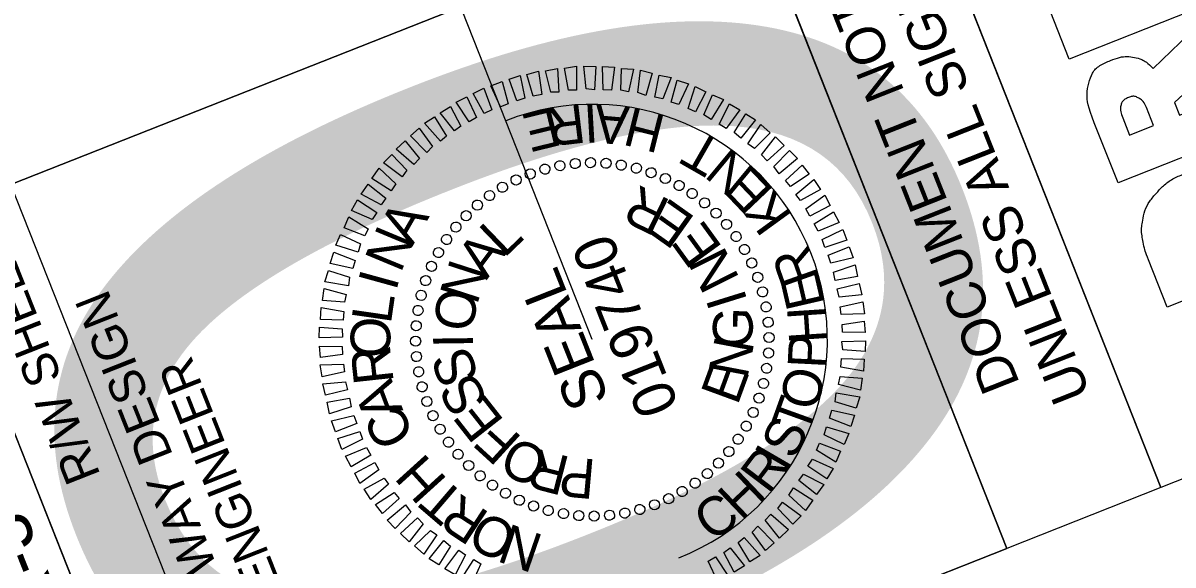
# Model space of a CAD drawing. Extents: x 1250793 to 1252430, y 745882 to 747850.
# Drawn here: x 1250893.3 to 1251056.5, y 747306.6 to 747383.5 of the extents above; entities that cross this region are included whole.
import ezdxf

# ---------------------------------------------------------------- set-up
doc = ezdxf.new("R2010")
doc.units = 0
for name, color, linetype in [('Pattern 1', 7, 'Continuous'), ('Scratch_Level_0', 7, 'Continuous'), ('Scratch_Level_1', 7, 'Continuous'), ('Sheet Data Field CELL', 7, 'Continuous'), ('Sheet Plan CELL', 7, 'Continuous'), ('Sheet Plan Layout CELL', 7, 'Continuous'), ('Sheet Professional Seal CELL', 7, 'Continuous'), ('Sheet Sticker Exception Certification CELL', 7, 'Continuous')]:
    doc.layers.add(name, color=color, linetype=linetype)

msp = doc.modelspace()

# ---------------------------------------------------------------- linework, layer by layer
at = {"layer": 'Pattern 1'}
for p, q in [((1251041.77, 747378.39), (1251039.05, 747385.27)), ((1251059.24, 747385.3), (1251041.77, 747378.39))]:
    msp.add_line(p, q, dxfattribs=at)
for points in [[(1251053.67, 747377.07), (1251060.06, 747383.24), (1251062.33, 747377.49), (1251056.73, 747372.28), (1251057.45, 747370.45), (1251064.08, 747373.07), (1251066.18, 747367.75), (1251048.7, 747360.84), (1251045.33, 747369.38)], [(1251049.36, 747370.1), (1251050.33, 747367.63), (1251053.75, 747368.98), (1251052.74, 747371.53)], [(1251070.59, 747356.61), (1251073.15, 747350.12), (1251055.68, 747343.21), (1251053.02, 747349.94)]]:
    msp.add_lwpolyline(points, dxfattribs=at)
for points in [[(1251045.33, 747369.38), (1251044.43, 747371.67), (1251044.17, 747373.55), (1251044.57, 747375.02), (1251044.97, 747376.5), (1251046.02, 747377.57), (1251047.73, 747378.25), (1251048.91, 747378.71), (1251050.01, 747378.85), (1251051.02, 747378.65), (1251052.04, 747378.45), (1251052.92, 747377.92), (1251053.67, 747377.07)], [(1251052.74, 747371.53), (1251052.5, 747372.15), (1251052.14, 747372.6), (1251051.66, 747372.86), (1251051.19, 747373.13), (1251050.7, 747373.17), (1251050.2, 747372.97), (1251049.63, 747372.74), (1251049.27, 747372.39), (1251049.13, 747371.91), (1251048.99, 747371.44), (1251049.07, 747370.83), (1251049.36, 747370.1)], [(1251053.02, 747349.94), (1251052.6, 747351), (1251052.32, 747351.98), (1251052.18, 747352.89), (1251052.03, 747353.8), (1251052.04, 747354.65), (1251052.18, 747355.43), (1251052.46, 747356.92), (1251053.14, 747358.26), (1251054.2, 747359.45), (1251055.26, 747360.63), (1251056.62, 747361.55), (1251058.26, 747362.2), (1251059.72, 747362.78), (1251061.2, 747363.03), (1251062.71, 747362.95), (1251064.21, 747362.87), (1251065.53, 747362.48), (1251066.68, 747361.77), (1251067.53, 747361.24), (1251068.27, 747360.56), (1251068.9, 747359.73), (1251069.53, 747358.89), (1251070.1, 747357.85), (1251070.59, 747356.61)]]:
    msp.add_open_spline(points, degree=3, dxfattribs=at)
at = {"layer": 'Scratch_Level_0'}
msp.add_lwpolyline([(1250981.23, 747503.62), (1251016.51, 747517.57), (1251090.07, 747331.55), (1251054.79, 747317.6)], close=True, dxfattribs=at)
msp.add_arc((1250974.08, 747338.64), 33.36, 291.5748, 111.5748, dxfattribs=at)
at = {"layer": 'Scratch_Level_1'}
for q in [(1250879.11, 747578.82), (1250974.08, 747338.64)]:
    msp.add_line((1250974.08, 747338.64), q, dxfattribs=at)
at = {"layer": 'Sheet Plan CELL'}
for p, q in [((1250916.72, 747262.99), (1250843.14, 747449)), ((1250916.72, 747262.99), (1250843.14, 747449)), ((1250891.55, 747360.62), (1250996.12, 747401.99))]:
    msp.add_line(p, q, dxfattribs=at)
for points in [[(1252347.85, 746430.97), (1251371.44, 746044.87), (1250893.39, 747253.76), (1251032.94, 747308.96), (1250959.39, 747494.98), (1251796.28, 747825.9)], [(1250891.55, 747360.62), (1250854.77, 747453.6), (1250959.39, 747494.98), (1250996.18, 747401.99)], [(1250893.39, 747253.76), (1250819.83, 747439.83), (1250843.14, 747449), (1250916.72, 747262.99)], [(1250928.33, 747267.58), (1250891.55, 747360.62), (1250996.18, 747401.99), (1251032.94, 747308.96)]]:
    msp.add_lwpolyline(points, close=True, dxfattribs=at)
at = {"layer": 'Sheet Professional Seal CELL'}
for p, q in [((1250971.62, 747363.63), (1250971.62, 747363.63)), ((1250973.83, 747363.76), (1250973.83, 747363.76)), ((1250976.02, 747363.65), (1250976.02, 747363.65)), ((1250978.2, 747363.44), (1250978.2, 747363.44)), ((1250965.27, 747362.15), (1250965.27, 747362.15)), ((1250967.37, 747362.81), (1250967.37, 747362.81)), ((1250969.5, 747363.28), (1250969.5, 747363.28)), ((1250980.33, 747362.94), (1250980.33, 747362.94)), ((1250982.46, 747362.33), (1250982.46, 747362.33)), ((1250961.35, 747360.22), (1250961.35, 747360.22)), ((1250963.24, 747361.29), (1250963.24, 747361.29)), ((1250984.45, 747361.5), (1250984.45, 747361.5)), ((1250986.45, 747360.52), (1250986.45, 747360.52)), ((1250959.46, 747359.04), (1250959.46, 747359.04)), ((1250988.26, 747359.35), (1250988.26, 747359.35)), ((1250957.72, 747357.71), (1250957.72, 747357.71)), ((1250990.03, 747358.01), (1250990.03, 747358.01)), ((1250956.16, 747356.23), (1250956.16, 747356.23)), ((1250991.67, 747356.56), (1250991.67, 747356.56)), ((1250954.71, 747354.58), (1250954.71, 747354.58)), ((1250993.15, 747355), (1250993.15, 747355)), ((1250953.37, 747352.81), (1250953.37, 747352.81)), ((1250994.48, 747353.27), (1250994.48, 747353.27)), ((1250952.2, 747351.01), (1250952.2, 747351.01)), ((1250995.66, 747351.37), (1250995.66, 747351.37)), ((1250951.22, 747349.01), (1250951.22, 747349.01)), ((1250996.73, 747349.48), (1250996.73, 747349.48)), ((1250997.59, 747347.45), (1250997.59, 747347.45)), ((1250950.39, 747347.01), (1250950.39, 747347.01)), ((1250949.78, 747344.89), (1250949.78, 747344.89)), ((1250998.26, 747345.35), (1250998.26, 747345.35)), ((1250949.28, 747342.76), (1250949.28, 747342.76)), ((1250998.72, 747343.22), (1250998.72, 747343.22)), ((1250949.07, 747340.58), (1250949.07, 747340.58)), ((1250999.08, 747341.1), (1250999.08, 747341.1)), ((1250999.2, 747338.89), (1250999.2, 747338.89)), ((1250948.97, 747338.39), (1250948.97, 747338.39)), ((1250974.08, 747338.64), (1250974.08, 747338.64)), ((1250949.09, 747336.17), (1250949.09, 747336.17)), ((1250999.1, 747336.7), (1250999.1, 747336.7)), ((1250949.44, 747334.06), (1250949.44, 747334.06)), ((1250998.88, 747334.52), (1250998.88, 747334.52)), ((1250998.38, 747332.39), (1250998.38, 747332.39)), ((1250949.91, 747331.93), (1250949.91, 747331.93)), ((1250950.58, 747329.83), (1250950.58, 747329.83)), ((1250997.77, 747330.26), (1250997.77, 747330.26)), ((1250951.43, 747327.8), (1250951.43, 747327.8)), ((1250996.95, 747328.27), (1250996.95, 747328.27)), ((1250952.5, 747325.91), (1250952.5, 747325.91)), ((1250995.96, 747326.27), (1250995.96, 747326.27)), ((1250994.8, 747324.46), (1250994.8, 747324.46)), ((1250953.68, 747324.01), (1250953.68, 747324.01)), ((1250993.45, 747322.69), (1250993.45, 747322.69)), ((1250955.01, 747322.28), (1250955.01, 747322.28)), ((1250992.01, 747321.05), (1250992.01, 747321.05)), ((1250956.49, 747320.71), (1250956.49, 747320.71)), ((1250990.44, 747319.57), (1250990.44, 747319.57)), ((1250958.14, 747319.27), (1250958.14, 747319.27)), ((1250959.91, 747317.92), (1250959.91, 747317.92)), ((1250988.71, 747318.24), (1250988.71, 747318.24)), ((1250961.71, 747316.76), (1250961.71, 747316.76)), ((1250986.81, 747317.06), (1250986.81, 747317.06)), ((1250963.71, 747315.77), (1250963.71, 747315.77)), ((1250965.71, 747314.95), (1250965.71, 747314.95)), ((1250980.79, 747314.46), (1250980.79, 747314.46)), ((1250982.89, 747315.13), (1250982.89, 747315.13)), ((1250984.92, 747315.99), (1250984.92, 747315.99)), ((1250967.83, 747314.34), (1250967.83, 747314.34)), ((1250969.96, 747313.84), (1250969.96, 747313.84)), ((1250972.15, 747313.62), (1250972.15, 747313.62)), ((1250974.34, 747313.52), (1250974.34, 747313.52)), ((1250976.55, 747313.64), (1250976.55, 747313.64)), ((1250978.66, 747314), (1250978.66, 747314))]:
    msp.add_line(p, q, dxfattribs=at)
for points in [[(1250965.7, 747373.17), (1250964.8, 747376.26), (1250966.45, 747376.7), (1250966.9, 747373.38)], [(1250968.21, 747373.74), (1250967.45, 747376.77), (1250969.16, 747377.07), (1250969.34, 747373.75)], [(1250970.69, 747374.02), (1250970.15, 747377.14), (1250971.81, 747377.42), (1250971.81, 747374.03)], [(1250973.19, 747374.2), (1250972.89, 747377.42), (1250974.57, 747377.38), (1250974.37, 747374.08)], [(1250975.61, 747374.08), (1250975.54, 747377.39), (1250977.25, 747377.26), (1250976.81, 747374.02)], [(1250978.11, 747374), (1250978.23, 747377.11), (1250979.94, 747376.98), (1250979.22, 747373.79)], [(1250980.55, 747373.67), (1250980.92, 747376.83), (1250982.59, 747376.41), (1250981.68, 747373.26)], [(1250961.03, 747371.65), (1250959.69, 747374.62), (1250961.28, 747375.24), (1250962.14, 747372.09)], [(1250963.37, 747372.52), (1250962.27, 747375.58), (1250963.84, 747376.1), (1250964.52, 747372.87)], [(1250982.96, 747373.01), (1250983.55, 747376.15), (1250985.25, 747375.8), (1250984.09, 747372.76)], [(1250985.28, 747372.32), (1250986.14, 747375.45), (1250987.75, 747374.91), (1250986.38, 747372)], [(1250958.72, 747370.69), (1250957.16, 747373.56), (1250958.7, 747374.28), (1250959.8, 747371.22)], [(1250987.69, 747371.39), (1250988.66, 747374.51), (1250990.19, 747373.77), (1250988.73, 747370.94)], [(1250989.93, 747370.5), (1250991.16, 747373.35), (1250992.72, 747372.68), (1250990.93, 747369.87)], [(1250954.53, 747368.22), (1250952.49, 747370.8), (1250953.96, 747371.71), (1250955.4, 747368.89)], [(1250956.6, 747369.52), (1250954.75, 747372.29), (1250956.28, 747373.05), (1250957.64, 747370.15)], [(1250992.1, 747369.21), (1250993.55, 747372.09), (1250995.02, 747371.22), (1250993.06, 747368.56)], [(1250952.52, 747366.78), (1250950.28, 747369.34), (1250951.7, 747370.22), (1250953.37, 747367.49)], [(1250994.2, 747367.99), (1250995.89, 747370.65), (1250997.25, 747369.79), (1250995.16, 747367.19)], [(1250950.59, 747365.16), (1250948.25, 747367.51), (1250949.49, 747368.6), (1250951.38, 747366.01)], [(1250996.17, 747366.41), (1250998, 747369.12), (1250999.31, 747367.97), (1250997.08, 747365.74)], [(1250948.73, 747363.46), (1250946.25, 747365.65), (1250947.5, 747366.84), (1250949.57, 747364.32)], [(1250998.08, 747364.85), (1251000.09, 747367.37), (1251001.31, 747366.18), (1250998.9, 747363.99)], [(1250999.86, 747363.19), (1251002.08, 747365.46), (1251003.19, 747364.29), (1251000.6, 747362.14)], [(1250947.1, 747361.73), (1250944.44, 747363.69), (1250945.64, 747364.87), (1250947.76, 747362.64)], [(1251001.51, 747361.2), (1251003.87, 747363.38), (1251004.86, 747362.1), (1251002.22, 747360.36)], [(1250945.53, 747359.72), (1250942.79, 747361.48), (1250943.84, 747362.92), (1250946.2, 747360.74)], [(1250944.1, 747357.75), (1250941.25, 747359.26), (1250942.25, 747360.68), (1250944.77, 747358.66)], [(1251002.99, 747359.21), (1251005.54, 747361.35), (1251006.49, 747359.89), (1251003.61, 747358.33)], [(1251004.39, 747357.18), (1251007.07, 747359.1), (1251007.82, 747357.62), (1251004.97, 747356.12)], [(1250942.84, 747355.64), (1250939.9, 747356.95), (1250940.77, 747358.43), (1250943.51, 747356.66)], [(1250941.81, 747353.35), (1250938.84, 747354.49), (1250939.51, 747356.05), (1250942.28, 747354.34)], [(1251005.55, 747355.06), (1251008.32, 747356.75), (1251009.13, 747355.24), (1251006.13, 747354)], [(1251006.7, 747352.83), (1251009.63, 747354.25), (1251010.19, 747352.7), (1251007.1, 747351.69)], [(1250940.85, 747351.04), (1250937.67, 747351.99), (1250938.35, 747353.54), (1250941.19, 747352.19)], [(1250940.1, 747348.7), (1250936.87, 747349.41), (1250937.41, 747351.02), (1250940.4, 747349.84)], [(1251007.54, 747350.58), (1251010.56, 747351.77), (1251011.12, 747350.22), (1251007.93, 747349.44)], [(1251008.32, 747348.2), (1251011.41, 747349.21), (1251011.74, 747347.56), (1251008.57, 747347.01)], [(1250939.46, 747346.24), (1250936.12, 747346.8), (1250936.62, 747348.4), (1250939.62, 747347.48)], [(1250938.92, 747343.93), (1250935.78, 747344.14), (1250936.02, 747345.85), (1250939.13, 747345.03)], [(1251008.83, 747345.82), (1251011.97, 747346.58), (1251012.34, 747344.95), (1251009.13, 747344.65)], [(1251009.25, 747343.24), (1251012.46, 747343.97), (1251012.71, 747342.25), (1251009.41, 747342.18)], [(1250938.7, 747341.37), (1250935.5, 747341.45), (1250935.58, 747343.15), (1250938.81, 747342.59)], [(1251009.53, 747340.77), (1251012.69, 747341.22), (1251012.79, 747339.59), (1251009.59, 747339.67)], [(1250938.64, 747338.93), (1250935.29, 747338.84), (1250935.33, 747340.36), (1250938.55, 747340.13)], [(1250938.63, 747336.5), (1250935.48, 747336.06), (1250935.37, 747337.69), (1250938.57, 747337.61)], [(1251009.52, 747338.35), (1251012.87, 747338.44), (1251012.83, 747336.92), (1251009.62, 747337.15)], [(1251009.47, 747335.91), (1251012.67, 747335.83), (1251012.59, 747334.13), (1251009.36, 747334.68)], [(1250938.91, 747334.03), (1250935.71, 747333.3), (1250935.45, 747335.03), (1250938.76, 747335.1)], [(1250939.34, 747331.46), (1250936.2, 747330.7), (1250935.82, 747332.33), (1250939.04, 747332.63)], [(1251009.24, 747333.35), (1251012.39, 747333.14), (1251012.15, 747331.43), (1251009.03, 747332.24)], [(1251008.7, 747331.04), (1251012.04, 747330.48), (1251011.55, 747328.88), (1251008.55, 747329.79)], [(1250939.85, 747329.08), (1250936.75, 747328.07), (1250936.43, 747329.72), (1250939.59, 747330.27)], [(1250940.63, 747326.7), (1250937.61, 747325.51), (1250937.05, 747327.06), (1250940.23, 747327.83)], [(1251008.06, 747328.58), (1251011.3, 747327.87), (1251010.76, 747326.26), (1251007.76, 747327.44)], [(1251007.32, 747326.24), (1251010.49, 747325.29), (1251009.82, 747323.73), (1251006.97, 747325.08)], [(1250941.46, 747324.45), (1250938.53, 747323.02), (1250937.97, 747324.58), (1250941.07, 747325.58)], [(1250942.62, 747322.22), (1250939.84, 747320.53), (1250939.03, 747322.04), (1250942.04, 747323.28)], [(1251006.35, 747323.92), (1251009.33, 747322.79), (1251008.66, 747321.23), (1251005.89, 747322.93)], [(1250943.78, 747320.1), (1250941.1, 747318.18), (1250940.35, 747319.65), (1250943.2, 747321.16)], [(1251005.32, 747321.64), (1251008.26, 747320.32), (1251007.39, 747318.85), (1251004.65, 747320.62)], [(1251004.06, 747319.52), (1251006.92, 747318.02), (1251005.92, 747316.6), (1251003.4, 747318.62)], [(1250945.17, 747318.07), (1250942.63, 747315.93), (1250941.68, 747317.38), (1250944.55, 747318.95)], [(1250946.66, 747316.07), (1250944.29, 747313.9), (1250943.3, 747315.18), (1250945.95, 747316.92)], [(1251002.63, 747317.56), (1251005.38, 747315.79), (1251004.33, 747314.36), (1251001.96, 747316.54)], [(1250948.3, 747314.09), (1250946.08, 747311.81), (1250944.98, 747312.99), (1250947.57, 747315.14)], [(1251001.07, 747315.54), (1251003.72, 747313.58), (1251002.52, 747312.41), (1251000.4, 747314.64)], [(1250950.09, 747312.43), (1250948.07, 747309.91), (1250946.85, 747311.1), (1250949.27, 747313.29)], [(1250999.43, 747313.82), (1251001.91, 747311.63), (1251000.66, 747310.44), (1250998.6, 747312.95)], [(1250952, 747310.87), (1250950.17, 747308.16), (1250948.85, 747309.31), (1250951.09, 747311.53)], [(1250997.58, 747312.12), (1250999.91, 747309.76), (1250998.67, 747308.68), (1250996.79, 747311.27)], [(1250953.97, 747309.29), (1250952.28, 747306.63), (1250950.91, 747307.49), (1250953, 747310.09)], [(1250995.64, 747310.49), (1250997.89, 747307.94), (1250996.46, 747307.06), (1250994.79, 747309.78)], [(1250956.06, 747308.07), (1250954.62, 747305.19), (1250953.15, 747306.06), (1250955.11, 747308.71)], [(1250993.63, 747309.05), (1250995.67, 747306.47), (1250994.2, 747305.57), (1250992.76, 747308.39)], [(1250958.24, 747306.78), (1250957, 747303.93), (1250955.44, 747304.6), (1250957.24, 747307.41)], [(1250991.56, 747307.75), (1250993.41, 747304.99), (1250991.88, 747304.22), (1250990.52, 747307.13)]]:
    msp.add_lwpolyline(points, close=True, dxfattribs=at)
for centre, major_axis in [((1250967.35, 747362.8), (-0.193, 0.694)), ((1250969.48, 747363.29), (-0.132, 0.708)), ((1250971.65, 747363.6), (-0.07, 0.717)), ((1250973.83, 747363.72), (-0.007, 0.72)), ((1250976.02, 747363.64), (0.056, 0.718)), ((1250978.19, 747363.38), (0.118, 0.71)), ((1250980.33, 747362.93), (0.179, 0.697)), ((1250963.26, 747361.26), (-0.311, 0.649)), ((1250965.27, 747362.12), (-0.253, 0.674)), ((1250982.42, 747362.29), (0.239, 0.679)), ((1250984.45, 747361.47), (0.298, 0.656)), ((1250961.33, 747360.23), (-0.366, 0.62)), ((1250986.4, 747360.48), (0.354, 0.627)), ((1250988.26, 747359.33), (0.407, 0.594)), ((1250957.77, 747357.69), (-0.468, 0.547)), ((1250959.49, 747359.04), (-0.419, 0.586)), ((1250990.01, 747358.01), (0.457, 0.556)), ((1250956.17, 747356.19), (-0.514, 0.504)), ((1250991.64, 747356.55), (0.504, 0.514)), ((1250954.71, 747354.57), (-0.556, 0.457)), ((1250993.13, 747354.95), (0.547, 0.468)), ((1250953.4, 747352.82), (-0.594, 0.407)), ((1250994.48, 747353.23), (0.586, 0.419)), ((1250995.68, 747351.4), (0.62, 0.366)), ((1250952.24, 747350.96), (-0.627, 0.354)), ((1250951.25, 747349.01), (-0.656, 0.298)), ((1250996.71, 747349.47), (0.649, 0.311)), ((1250950.43, 747346.98), (-0.679, 0.239)), ((1250997.56, 747347.45), (0.674, 0.253)), ((1250949.79, 747344.89), (-0.697, 0.179)), ((1250998.24, 747345.37), (0.694, 0.193)), ((1250998.74, 747343.24), (0.708, 0.132)), ((1250949.34, 747342.75), (-0.71, 0.118)), ((1250949.08, 747340.57), (-0.718, 0.056)), ((1250999.04, 747341.07), (0.717, 0.07)), ((1250949, 747338.39), (-0.72, -0.007)), ((1250999.16, 747338.89), (0.72, 0.007)), ((1250999.09, 747336.7), (0.718, -0.056)), ((1250949.12, 747336.2), (-0.717, -0.07)), ((1250949.43, 747334.04), (-0.708, -0.132)), ((1250998.82, 747334.53), (0.71, -0.118)), ((1250949.92, 747331.9), (-0.694, -0.193)), ((1250998.37, 747332.39), (0.697, -0.179)), ((1250997.73, 747330.3), (0.679, -0.239)), ((1250950.6, 747329.82), (-0.674, -0.253)), ((1250996.92, 747328.27), (0.656, -0.298)), ((1250951.46, 747327.81), (-0.649, -0.311)), ((1250952.49, 747325.88), (-0.62, -0.366)), ((1250995.93, 747326.32), (0.627, -0.354)), ((1250953.68, 747324.05), (-0.586, -0.419)), ((1250994.77, 747324.46), (0.594, -0.407)), ((1250955.03, 747322.33), (-0.547, -0.468)), ((1250993.46, 747322.71), (0.556, -0.457)), ((1250956.53, 747320.73), (-0.504, -0.514)), ((1250991.99, 747321.08), (0.514, -0.504)), ((1250958.16, 747319.27), (-0.457, -0.556)), ((1250990.4, 747319.59), (0.468, -0.547)), ((1250959.9, 747317.95), (-0.407, -0.594)), ((1250986.84, 747317.05), (0.366, -0.62)), ((1250988.67, 747318.24), (0.419, -0.586)), ((1250961.76, 747316.79), (-0.354, -0.627)), ((1250963.71, 747315.8), (-0.298, -0.656)), ((1250984.91, 747316.02), (0.311, -0.649)), ((1250965.74, 747314.99), (-0.239, -0.679)), ((1250967.83, 747314.35), (-0.179, -0.697)), ((1250969.98, 747313.9), (-0.118, -0.71)), ((1250972.15, 747313.63), (-0.056, -0.718)), ((1250976.52, 747313.68), (0.07, -0.717)), ((1250978.69, 747313.98), (0.132, -0.708)), ((1250980.82, 747314.48), (0.193, -0.694)), ((1250982.9, 747315.16), (0.253, -0.674)), ((1250974.33, 747313.56), (0.007, -0.72))]:
    msp.add_ellipse(centre, major_axis=major_axis, ratio=0.999708, dxfattribs=at)
at = {"layer": 'Sheet Sticker Exception Certification CELL'}
for p, q in [((1250981.23, 747503.62), (1251054.79, 747317.6)), ((1250981.23, 747503.62), (1251054.79, 747317.6)), ((1251032.94, 747308.96), (1250959.38, 747494.98)), ((1251032.94, 747308.96), (1250959.38, 747494.98)), ((1251054.79, 747317.6), (1251032.94, 747308.96)), ((1251054.79, 747317.6), (1251032.94, 747308.96))]:
    msp.add_line(p, q, dxfattribs=at)

# ---------------------------------------------------------------- texts
at = {"layer": 'Sheet Data Field CELL'}
msp.add_text('R-3430B', height=7.5, rotation=111.5744, dxfattribs=at).set_placement((1250899.24, 747299.7))
at = {"layer": 'Sheet Plan CELL'}
for s, height, p in [('R/W SHEET NO.', 5.0001, (1250904.31, 747319.37)), ('ROADWAY DESIGN', 5.0001, (1250928, 747288.28)), ('ENGINEER', 5, (1250929.86, 747304.06))]:
    msp.add_text(s, height=height, rotation=111.5744, dxfattribs=at).set_placement(p)
at = {"layer": 'Sheet Plan Layout CELL'}
msp.add_text('04', height=131.25, rotation=111.5743, dxfattribs=at).set_placement((1251042.72, 747314.2))
at = {"layer": 'Sheet Professional Seal CELL'}
for s, height, rotation, p in [('E', 5.5, 193.7573, (1250968.66, 747371.66)), ('R', 5.5, 186.8309, (1250972.68, 747372.07)), ('I', 5.5, 183.3104, (1250974.74, 747372.1)), ('A', 5.5, 175.1246, (1250979.49, 747371.66)), ('H', 5.5, 165.8798, (1250984.73, 747370.36)), ('T', 5.5, 150.1379, (1250992.94, 747366.29)), ('N', 5.5, 140.2062, (1250997.42, 747362.62)), ('E', 5.5, 133.6232, (1251000.02, 747359.79)), ('R', 5.64, 154.0562, (1250985.4, 747358.28)), ('E', 5.64, 144.6989, (1250988.89, 747355.84)), ('K', 5.5, 125.9526, (1251002.61, 747356.14)), ('A', 5.64, 60.1919, (1250948.52, 747351.76)), ('E', 5.64, 125.9865, (1250992.66, 747351.63)), ('N', 5.64, 67.3937, (1250946.86, 747347.93)), ('L', 5.64, 43.9756, (1250961.55, 747350.08)), ('A', 5.64, 53.335, (1250959.06, 747347)), ('019740', 5.998, 111.5748, (1250986.44, 747329.15)), ('R', 5.5, 109.581, (1251006.38, 747347.39)), ('N', 5.64, 116.6312, (1250995.04, 747347.25)), ('N', 5.64, 72.0514, (1250957.69, 747343.39)), ('SEAL', 5.998, 111.5748, (1250976.53, 747330.14)), ('I', 5.64, 74.5949, (1250946.21, 747345.36)), ('E', 5.5, 102.998, (1251007.17, 747343.63)), ('O', 5.64, 81.4083, (1250957.06, 747339.54)), ('I', 5.64, 107.276, (1250996.13, 747344.08)), ('L', 5.64, 81.7957, (1250945.47, 747340.71)), ('G', 5.64, 88.565, (1250996.77, 747337.29)), ('H', 5.5, 93.7532, (1251007.54, 747338.24)), ('O', 5.64, 88.9959, (1250945.36, 747335.94)), ('P', 5.5, 87.1702, (1251007.28, 747334.41)), ('R', 5.64, 96.1959, (1250945.9, 747332.55)), ('I', 5.64, 90.7644, (1250957.14, 747337.42)), ('S', 5.64, 109.4752, (1250958.07, 747333.17)), ('N', 5.64, 79.2087, (1250996.07, 747332.92)), ('E', 5.64, 69.8517, (1250994.67, 747329.14)), ('O', 5.5, 76.4657, (1251005.92, 747328.32)), ('A', 5.64, 110.5951, (1250947.26, 747328.57)), ('S', 5.64, 118.8304, (1250959.44, 747329.84)), ('E', 5.64, 128.1858, (1250961.69, 747327.02)), ('T', 5.5, 70.169, (1251004.59, 747324.89)), ('C', 5.64, 117.7946, (1250948.99, 747325.01)), ('S', 5.5, 63.3856, (1251002.75, 747321.38)), ('F', 5.64, 137.5418, (1250964.26, 747324.59)), ('O', 5.64, 156.256, (1250968.22, 747322.61)), ('R', 5.64, 165.6144, (1250971.14, 747321.88)), ('R', 5.5, 52.9387, (1250999.15, 747316.47)), ('I', 5.5, 59.8652, (1251001.64, 747319.65)), ('H', 5.64, 132.1943, (1250953.64, 747318.67)), ('P', 5.64, 174.9737, (1250974.7, 747321.57)), ('H', 5.5, 43.6939, (1250995.26, 747312.73)), ('T', 5.64, 139.3946, (1250956.37, 747316.26)), ('R', 5.64, 146.5953, (1250959.67, 747313.91)), ('C', 5.5, 34.8212, (1250991.01, 747309.77)), ('O', 5.64, 153.7965, (1250963.82, 747311.84)), ('N', 5.64, 160.9983, (1250967.36, 747310.76))]:
    msp.add_text(s, height=height, rotation=rotation, dxfattribs=at).set_placement(p)
at = {"layer": 'Sheet Sticker Exception Certification CELL'}
for s, p in [('UNLESS ALL SIGNATURES COMPLETED', (1251044.86, 747330.87)), ('UNLESS ALL SIGNATURES COMPLETED', (1251044.86, 747330.87)), ('DOCUMENT NOT CONSIDERED FINAL', (1251034.81, 747332.35)), ('DOCUMENT NOT CONSIDERED FINAL', (1251034.81, 747332.35))]:
    msp.add_text(s, height=5.5, rotation=111.5743, dxfattribs=at).set_placement(p)

doc.saveas('drawing.dxf')
